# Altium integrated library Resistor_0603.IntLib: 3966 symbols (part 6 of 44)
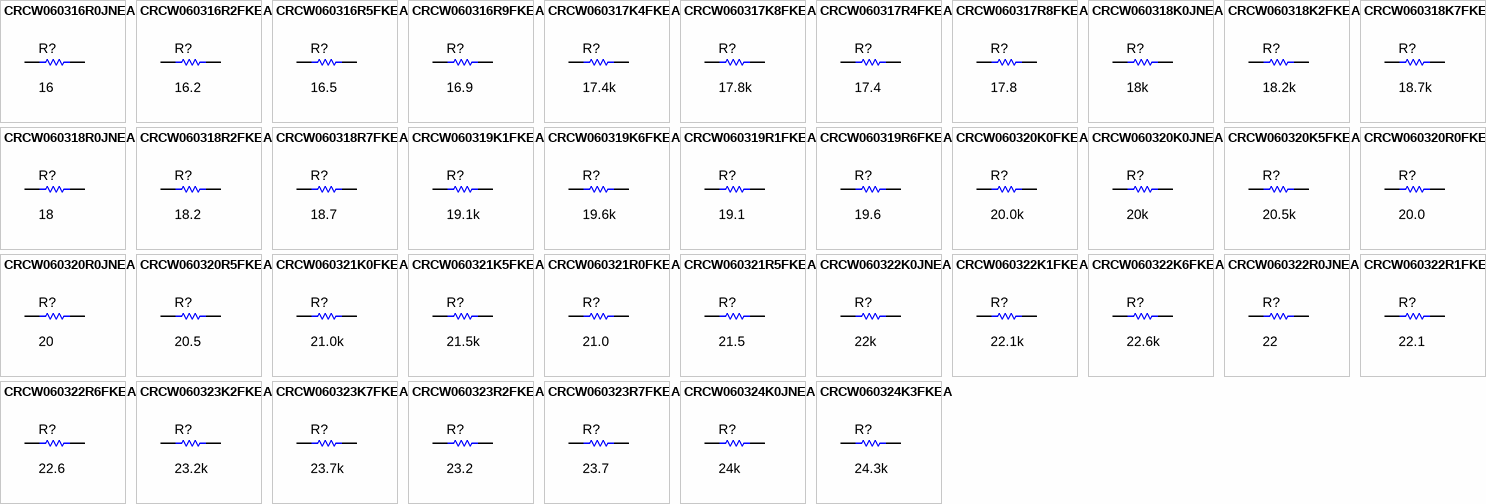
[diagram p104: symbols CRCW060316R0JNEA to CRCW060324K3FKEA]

## CRCW060318K0JNEA
designator R?  ValueDisplayed: 18k  (hidden comment: CRCW060318K0JNEA)
RES, 18 k, 5%, 0.1 W, 0603; Manufacturer: Vishay-Dale; CompType: Resistor; Value: 18k; Res_ohm: 18000; Value_Code: 18k0; Tolerance_%: 5; Power_W: 0.1; Value2: 0.1W; VDC_V: 75; TempCo: 200 ppm/C; SizeArea_mm2: 1.28; SizeX_mm: 1.6; SizeY_mm: 0.8; SizeZ_mm: 1; EIA_Code: E24; U/M: EA; AEC Category: Q200; Green_Lifecycle: Active; Green_REACh: Passed
signal-integrity model Resistor
simulation model Resistor
footprint 0603
footprint 0603M
footprint 0603L
footprint 0603_HV
footprint 0603S
pins: 1, 2

## CRCW060318K2FKEA
designator R?  ValueDisplayed: 18.2k  (hidden comment: CRCW060318K2FKEA)
RES, 18.2 k, 1%, 0.1 W, 0603; Manufacturer: Vishay-Dale; CompType: Resistor; Value: 18.2k; Res_ohm: 18200; Value_Code: 18k2; Tolerance_%: 1; Power_W: 0.1; Value2: 0.1W; VDC_V: 75; TempCo: 100 ppm/C; SizeArea_mm2: 1.28; SizeX_mm: 1.6; SizeY_mm: 0.8; EIA_Code: E96; U/M: EA; AEC Category: Q200; Green_Lifecycle: Active; Green_REACh: Passed
signal-integrity model Resistor
simulation model Resistor
footprint 0603
footprint 0603M
footprint 0603L
footprint 0603_HV
footprint 0603S
pins: 1, 2

## CRCW060318K7FKEA
designator R?  ValueDisplayed: 18.7k  (hidden comment: CRCW060318K7FKEA)
RES, 18.7 k, 1%, 0.1 W, 0603; Manufacturer: Vishay-Dale; CompType: Resistor; Value: 18.7k; Res_ohm: 18700; Value_Code: 18k7; Tolerance_%: 1; Power_W: 0.1; Value2: 0.1W; VDC_V: 75; TempCo: 100 ppm/C; SizeArea_mm2: 1.28; SizeX_mm: 1.6; SizeY_mm: 0.8; EIA_Code: E96; U/M: EA; AEC Category: Q200; Green_Lifecycle: Active; Green_REACh: Passed
signal-integrity model Resistor
simulation model Resistor
footprint 0603
footprint 0603M
footprint 0603L
footprint 0603_HV
footprint 0603S
pins: 1, 2

## CRCW060318R0JNEA
designator R?  ValueDisplayed: 18  (hidden comment: CRCW060318R0JNEA)
RES, 18, 5%, 0.1 W, 0603; Manufacturer: Vishay-Dale; CompType: Resistor; Value: 18; Value_Code: 18R0; Tolerance_%: 5; Power_W: 0.1; Value2: 0.1W; VDC_V: 75; TempCo: 200 ppm/C; SizeArea_mm2: 1.28; SizeX_mm: 1.6; SizeY_mm: 0.8; SizeZ_mm: 1; EIA_Code: E24; U/M: EA; AEC Category: Q200; Green_Lifecycle: Active; Green_REACh: Passed
signal-integrity model Resistor
simulation model Resistor
footprint 0603
footprint 0603M
footprint 0603L
footprint 0603_HV
footprint 0603S
pins: 1, 2

## CRCW060318R2FKEA
designator R?  ValueDisplayed: 18.2  (hidden comment: CRCW060318R2FKEA)
RES, 18.2, 1%, 0.1 W, 0603; Manufacturer: Vishay-Dale; CompType: Resistor; Value: 18.2; Value_Code: 18R2; Tolerance_%: 1; Power_W: 0.1; Value2: 0.1W; VDC_V: 75; TempCo: 100 ppm/C; SizeArea_mm2: 1.28; SizeX_mm: 1.6; SizeY_mm: 0.8; EIA_Code: E96; U/M: EA; AEC Category: Q200
signal-integrity model Resistor
simulation model Resistor
footprint 0603
footprint 0603M
footprint 0603L
footprint 0603_HV
footprint 0603S
pins: 1, 2

## CRCW060318R7FKEA
designator R?  ValueDisplayed: 18.7  (hidden comment: CRCW060318R7FKEA)
RES, 18.7, 1%, 0.1 W, 0603; Manufacturer: Vishay-Dale; CompType: Resistor; Value: 18.7; Value_Code: 18R7; Tolerance_%: 1; Power_W: 0.1; Value2: 0.1W; VDC_V: 75; TempCo: 100 ppm/C; SizeArea_mm2: 1.28; SizeX_mm: 1.6; SizeY_mm: 0.8; EIA_Code: E96; U/M: EA; AEC Category: Q200
signal-integrity model Resistor
simulation model Resistor
footprint 0603
footprint 0603M
footprint 0603L
footprint 0603_HV
footprint 0603S
pins: 1, 2

## CRCW060319K1FKEA
designator R?  ValueDisplayed: 19.1k  (hidden comment: CRCW060319K1FKEA)
RES, 19.1 k, 1%, 0.1 W, 0603; Manufacturer: Vishay-Dale; CompType: Resistor; Value: 19.1k; Res_ohm: 19100; Value_Code: 19k1; Tolerance_%: 1; Power_W: 0.1; Value2: 0.1W; VDC_V: 75; TempCo: 100 ppm/C; SizeArea_mm2: 1.28; SizeX_mm: 1.6; SizeY_mm: 0.8; EIA_Code: E96; U/M: EA; AEC Category: Q200; Green_Lifecycle: Active; Green_REACh: Passed
signal-integrity model Resistor
simulation model Resistor
footprint 0603
footprint 0603M
footprint 0603L
footprint 0603_HV
footprint 0603S
pins: 1, 2

## CRCW060319K6FKEA
designator R?  ValueDisplayed: 19.6k  (hidden comment: CRCW060319K6FKEA)
RES, 19.6 k, 1%, 0.1 W, 0603; Manufacturer: Vishay-Dale; CompType: Resistor; Value: 19.6k; Res_ohm: 19600; Value_Code: 19k6; Tolerance_%: 1; Power_W: 0.1; Value2: 0.1W; VDC_V: 75; TempCo: 100 ppm/C; SizeArea_mm2: 1.28; SizeX_mm: 1.6; SizeY_mm: 0.8; EIA_Code: E96; U/M: EA; AEC Category: Q200; Green_Lifecycle: Active; Green_REACh: Passed
signal-integrity model Resistor
simulation model Resistor
footprint 0603
footprint 0603M
footprint 0603L
footprint 0603_HV
footprint 0603S
pins: 1, 2

## CRCW060319R1FKEA
designator R?  ValueDisplayed: 19.1  (hidden comment: CRCW060319R1FKEA)
RES, 19.1, 1%, 0.1 W, 0603; Manufacturer: Vishay-Dale; CompType: Resistor; Value: 19.1; Value_Code: 19R1; Tolerance_%: 1; Power_W: 0.1; Value2: 0.1W; VDC_V: 75; TempCo: 100 ppm/C; SizeArea_mm2: 1.28; SizeX_mm: 1.6; SizeY_mm: 0.8; EIA_Code: E96; U/M: EA; AEC Category: Q200
signal-integrity model Resistor
simulation model Resistor
footprint 0603
footprint 0603M
footprint 0603L
footprint 0603_HV
footprint 0603S
pins: 1, 2

## CRCW060319R6FKEA
designator R?  ValueDisplayed: 19.6  (hidden comment: CRCW060319R6FKEA)
RES, 19.6, 1%, 0.1 W, 0603; Manufacturer: Vishay-Dale; CompType: Resistor; Value: 19.6; Value_Code: 19R6; Tolerance_%: 1; Power_W: 0.1; Value2: 0.1W; VDC_V: 75; TempCo: 100 ppm/C; SizeArea_mm2: 1.28; SizeX_mm: 1.6; SizeY_mm: 0.8; EIA_Code: E96; U/M: EA; AEC Category: Q200
signal-integrity model Resistor
simulation model Resistor
footprint 0603
footprint 0603M
footprint 0603L
footprint 0603_HV
footprint 0603S
pins: 1, 2

## CRCW060320K0FKEA
designator R?  ValueDisplayed: 20.0k  (hidden comment: CRCW060320K0FKEA)
RES, 20.0 k, 1%, 0.1 W, 0603; Manufacturer: Vishay-Dale; CompType: Resistor; Value: 20.0k; Res_ohm: 20000; Value_Code: 20k0; Tolerance_%: 1; Power_W: 0.1; Value2: 0.1W; VDC_V: 75; TempCo: 100 ppm/C; SizeArea_mm2: 1.28; SizeX_mm: 1.6; SizeY_mm: 0.8; EIA_Code: E96; U/M: EA; AEC Category: Q200; Green_Lifecycle: Active; Green_REACh: Passed
signal-integrity model Resistor
simulation model Resistor
footprint 0603
footprint 0603M
footprint 0603L
footprint 0603_HV
footprint 0603S
pins: 1, 2

## CRCW060320K0JNEA
designator R?  ValueDisplayed: 20k  (hidden comment: CRCW060320K0JNEA)
RES, 20 k, 5%, 0.1 W, 0603; Manufacturer: Vishay-Dale; CompType: Resistor; Value: 20k; Res_ohm: 20000; Value_Code: 20k0; Tolerance_%: 5; Power_W: 0.1; Value2: 0.1W; VDC_V: 75; TempCo: 200 ppm/C; SizeArea_mm2: 1.28; SizeX_mm: 1.6; SizeY_mm: 0.8; SizeZ_mm: 1; EIA_Code: E24; U/M: EA; AEC Category: Q200; Green_Lifecycle: Active; Green_REACh: Passed
signal-integrity model Resistor
simulation model Resistor
footprint 0603
footprint 0603M
footprint 0603L
footprint 0603_HV
footprint 0603S
pins: 1, 2

## CRCW060320K5FKEA
designator R?  ValueDisplayed: 20.5k  (hidden comment: CRCW060320K5FKEA)
RES, 20.5 k, 1%, 0.1 W, 0603; Manufacturer: Vishay-Dale; CompType: Resistor; Value: 20.5k; Res_ohm: 20500; Value_Code: 20k5; Tolerance_%: 1; Power_W: 0.1; Value2: 0.1W; VDC_V: 75; TempCo: 100 ppm/C; SizeArea_mm2: 1.28; SizeX_mm: 1.6; SizeY_mm: 0.8; EIA_Code: E96; U/M: EA; AEC Category: Q200; Green_Lifecycle: Active; Green_REACh: Passed
signal-integrity model Resistor
simulation model Resistor
footprint 0603
footprint 0603M
footprint 0603L
footprint 0603_HV
footprint 0603S
pins: 1, 2

## CRCW060320R0FKEA
designator R?  ValueDisplayed: 20.0  (hidden comment: CRCW060320R0FKEA)
RES, 20.0, 1%, 0.1 W, 0603; Manufacturer: Vishay-Dale; CompType: Resistor; Value: 20.0; Res_ohm: 20; Value_Code: 20R0; Tolerance_%: 1; Power_W: 0.1; Value2: 0.1W; VDC_V: 75; TempCo: 100 ppm/C; SizeArea_mm2: 1.28; SizeX_mm: 1.6; SizeY_mm: 0.8; EIA_Code: E96; U/M: EA; AEC Category: Q200; Green_Lifecycle: Active; Green_REACh: Passed
signal-integrity model Resistor
simulation model Resistor
footprint 0603
footprint 0603M
footprint 0603L
footprint 0603_HV
footprint 0603S
pins: 1, 2

## CRCW060320R0JNEA
designator R?  ValueDisplayed: 20  (hidden comment: CRCW060320R0JNEA)
RES, 20, 5%, 0.1 W, 0603; Manufacturer: Vishay-Dale; CompType: Resistor; Value: 20; Value_Code: 20R0; Tolerance_%: 5; Power_W: 0.1; Value2: 0.1W; VDC_V: 75; TempCo: 200 ppm/C; SizeArea_mm2: 1.28; SizeX_mm: 1.6; SizeY_mm: 0.8; SizeZ_mm: 1; EIA_Code: E24; U/M: EA; AEC Category: Q200
signal-integrity model Resistor
simulation model Resistor
footprint 0603
footprint 0603M
footprint 0603L
footprint 0603_HV
footprint 0603S
pins: 1, 2

## CRCW060320R5FKEA
designator R?  ValueDisplayed: 20.5  (hidden comment: CRCW060320R5FKEA)
RES, 20.5, 1%, 0.1 W, 0603; Manufacturer: Vishay-Dale; CompType: Resistor; Value: 20.5; Value_Code: 20R5; Tolerance_%: 1; Power_W: 0.1; Value2: 0.1W; VDC_V: 75; TempCo: 100 ppm/C; SizeArea_mm2: 1.28; SizeX_mm: 1.6; SizeY_mm: 0.8; EIA_Code: E96; U/M: EA; AEC Category: Q200
signal-integrity model Resistor
simulation model Resistor
footprint 0603
footprint 0603M
footprint 0603L
footprint 0603_HV
footprint 0603S
pins: 1, 2

## CRCW060321K0FKEA
designator R?  ValueDisplayed: 21.0k  (hidden comment: CRCW060321K0FKEA)
RES, 21.0 k, 1%, 0.1 W, 0603; Manufacturer: Vishay-Dale; CompType: Resistor; Value: 21.0k; Res_ohm: 21000; Value_Code: 21k0; Tolerance_%: 1; Power_W: 0.1; Value2: 0.1W; VDC_V: 75; TempCo: 100 ppm/C; SizeArea_mm2: 1.28; SizeX_mm: 1.6; SizeY_mm: 0.8; EIA_Code: E96; U/M: EA; AEC Category: Q200
signal-integrity model Resistor
simulation model Resistor
footprint 0603
footprint 0603M
footprint 0603L
footprint 0603_HV
footprint 0603S
pins: 1, 2

## CRCW060321K5FKEA
designator R?  ValueDisplayed: 21.5k  (hidden comment: CRCW060321K5FKEA)
RES, 21.5 k, 1%, 0.1 W, 0603; Manufacturer: Vishay-Dale; CompType: Resistor; Value: 21.5k; Res_ohm: 21500; Value_Code: 21k5; Tolerance_%: 1; Power_W: 0.1; Value2: 0.1W; VDC_V: 75; TempCo: 100 ppm/C; SizeArea_mm2: 1.28; SizeX_mm: 1.6; SizeY_mm: 0.8; EIA_Code: E96; U/M: EA; AEC Category: Q200; Green_Lifecycle: Active; Green_REACh: Passed
signal-integrity model Resistor
simulation model Resistor
footprint 0603
footprint 0603M
footprint 0603L
footprint 0603_HV
footprint 0603S
pins: 1, 2

## CRCW060321R0FKEA
designator R?  ValueDisplayed: 21.0  (hidden comment: CRCW060321R0FKEA)
RES, 21.0, 1%, 0.1 W, 0603; Manufacturer: Vishay-Dale; CompType: Resistor; Value: 21.0; Res_ohm: 21; Value_Code: 21R0; Tolerance_%: 1; Power_W: 0.1; Value2: 0.1W; VDC_V: 75; TempCo: 100 ppm/C; SizeArea_mm2: 1.28; SizeX_mm: 1.6; SizeY_mm: 0.8; EIA_Code: E96; U/M: EA; AEC Category: Q200
signal-integrity model Resistor
simulation model Resistor
footprint 0603
footprint 0603M
footprint 0603L
footprint 0603_HV
footprint 0603S
pins: 1, 2

## CRCW060321R5FKEA
designator R?  ValueDisplayed: 21.5  (hidden comment: CRCW060321R5FKEA)
RES, 21.5, 1%, 0.1 W, 0603; Manufacturer: Vishay-Dale; CompType: Resistor; Value: 21.5; Value_Code: 21R5; Tolerance_%: 1; Power_W: 0.1; Value2: 0.1W; VDC_V: 75; TempCo: 100 ppm/C; SizeArea_mm2: 1.28; SizeX_mm: 1.6; SizeY_mm: 0.8; EIA_Code: E96; U/M: EA; AEC Category: Q200
signal-integrity model Resistor
simulation model Resistor
footprint 0603
footprint 0603M
footprint 0603L
footprint 0603_HV
footprint 0603S
pins: 1, 2

## CRCW060322K0JNEA
designator R?  ValueDisplayed: 22k  (hidden comment: CRCW060322K0JNEA)
RES, 22 k, 5%, 0.1 W, 0603; Manufacturer: Vishay-Dale; CompType: Resistor; Value: 22k; Res_ohm: 22000; Value_Code: 22k0; Tolerance_%: 5; Power_W: 0.1; Value2: 0.1W; VDC_V: 75; TempCo: 200 ppm/C; SizeArea_mm2: 1.28; SizeX_mm: 1.6; SizeY_mm: 0.8; SizeZ_mm: 1; EIA_Code: E24; U/M: EA; AEC Category: Q200; Green_Lifecycle: Active; Green_REACh: Passed
signal-integrity model Resistor
simulation model Resistor
footprint 0603
footprint 0603M
footprint 0603L
footprint 0603_HV
footprint 0603S
pins: 1, 2

## CRCW060322K1FKEA
designator R?  ValueDisplayed: 22.1k  (hidden comment: CRCW060322K1FKEA)
RES, 22.1 k, 1%, 0.1 W, 0603; Manufacturer: Vishay-Dale; CompType: Resistor; Value: 22.1k; Res_ohm: 22100; Value_Code: 22k1; Tolerance_%: 1; Power_W: 0.1; Value2: 0.1W; VDC_V: 75; TempCo: 100 ppm/C; SizeArea_mm2: 1.28; SizeX_mm: 1.6; SizeY_mm: 0.8; EIA_Code: E96; U/M: EA; AEC Category: Q200; Green_Lifecycle: Active; Green_REACh: Passed
signal-integrity model Resistor
simulation model Resistor
footprint 0603
footprint 0603M
footprint 0603L
footprint 0603_HV
footprint 0603S
pins: 1, 2

## CRCW060322K6FKEA
designator R?  ValueDisplayed: 22.6k  (hidden comment: CRCW060322K6FKEA)
RES, 22.6 k, 1%, 0.1 W, 0603; Manufacturer: Vishay-Dale; CompType: Resistor; Value: 22.6k; Res_ohm: 22600; Value_Code: 22k6; Tolerance_%: 1; Power_W: 0.1; Value2: 0.1W; VDC_V: 75; TempCo: 100 ppm/C; SizeArea_mm2: 1.28; SizeX_mm: 1.6; SizeY_mm: 0.8; EIA_Code: E96; U/M: EA; AEC Category: Q200; Green_Lifecycle: Active; Green_REACh: Passed
signal-integrity model Resistor
simulation model Resistor
footprint 0603
footprint 0603M
footprint 0603L
footprint 0603_HV
footprint 0603S
pins: 1, 2

## CRCW060322R0JNEA
designator R?  ValueDisplayed: 22  (hidden comment: CRCW060322R0JNEA)
RES, 22, 5%, 0.1 W, 0603; Manufacturer: Vishay-Dale; CompType: Resistor; Value: 22; Value_Code: 22R0; Tolerance_%: 5; Power_W: 0.1; Value2: 0.1W; VDC_V: 75; TempCo: 200 ppm/C; SizeArea_mm2: 1.28; SizeX_mm: 1.6; SizeY_mm: 0.8; SizeZ_mm: 1; EIA_Code: E24; U/M: EA; AEC Category: Q200
signal-integrity model Resistor
simulation model Resistor
footprint 0603
footprint 0603M
footprint 0603L
footprint 0603_HV
footprint 0603S
pins: 1, 2

## CRCW060322R1FKEA
designator R?  ValueDisplayed: 22.1  (hidden comment: CRCW060322R1FKEA)
RES, 22.1, 1%, 0.1 W, 0603; Manufacturer: Vishay-Dale; CompType: Resistor; Value: 22.1; Value_Code: 22R1; Tolerance_%: 1; Power_W: 0.1; Value2: 0.1W; VDC_V: 75; TempCo: 100 ppm/C; SizeArea_mm2: 1.28; SizeX_mm: 1.6; SizeY_mm: 0.8; EIA_Code: E96; U/M: EA; AEC Category: Q200; Green_Lifecycle: Active; Green_REACh: Passed
signal-integrity model Resistor
simulation model Resistor
footprint 0603
footprint 0603M
footprint 0603L
footprint 0603_HV
footprint 0603S
pins: 1, 2

## CRCW060322R6FKEA
designator R?  ValueDisplayed: 22.6  (hidden comment: CRCW060322R6FKEA)
RES, 22.6, 1%, 0.1 W, 0603; Manufacturer: Vishay-Dale; CompType: Resistor; Value: 22.6; Value_Code: 22R6; Tolerance_%: 1; Power_W: 0.1; Value2: 0.1W; VDC_V: 75; TempCo: 100 ppm/C; SizeArea_mm2: 1.28; SizeX_mm: 1.6; SizeY_mm: 0.8; EIA_Code: E96; U/M: EA; AEC Category: Q200
signal-integrity model Resistor
simulation model Resistor
footprint 0603
footprint 0603M
footprint 0603L
footprint 0603_HV
footprint 0603S
pins: 1, 2

## CRCW060323K2FKEA
designator R?  ValueDisplayed: 23.2k  (hidden comment: CRCW060323K2FKEA)
RES, 23.2 k, 1%, 0.1 W, 0603; Manufacturer: Vishay-Dale; CompType: Resistor; Value: 23.2k; Res_ohm: 23200; Value_Code: 23k2; Tolerance_%: 1; Power_W: 0.1; Value2: 0.1W; VDC_V: 75; TempCo: 100 ppm/C; SizeArea_mm2: 1.28; SizeX_mm: 1.6; SizeY_mm: 0.8; EIA_Code: E96; U/M: EA; AEC Category: Q200; Green_Lifecycle: Active; Green_REACh: Passed
signal-integrity model Resistor
simulation model Resistor
footprint 0603
footprint 0603M
footprint 0603L
footprint 0603_HV
footprint 0603S
pins: 1, 2

## CRCW060323K7FKEA
designator R?  ValueDisplayed: 23.7k  (hidden comment: CRCW060323K7FKEA)
RES, 23.7 k, 1%, 0.1 W, 0603; Manufacturer: Vishay-Dale; CompType: Resistor; Value: 23.7k; Res_ohm: 23700; Value_Code: 23k7; Tolerance_%: 1; Power_W: 0.1; Value2: 0.1W; VDC_V: 75; TempCo: 100 ppm/C; SizeArea_mm2: 1.28; SizeX_mm: 1.6; SizeY_mm: 0.8; EIA_Code: E96; U/M: EA; AEC Category: Q200
signal-integrity model Resistor
simulation model Resistor
footprint 0603
footprint 0603M
footprint 0603L
footprint 0603_HV
footprint 0603S
pins: 1, 2

## CRCW060323R2FKEA
designator R?  ValueDisplayed: 23.2  (hidden comment: CRCW060323R2FKEA)
RES, 23.2, 1%, 0.1 W, 0603; Manufacturer: Vishay-Dale; CompType: Resistor; Value: 23.2; Value_Code: 23R2; Tolerance_%: 1; Power_W: 0.1; Value2: 0.1W; VDC_V: 75; TempCo: 100 ppm/C; SizeArea_mm2: 1.28; SizeX_mm: 1.6; SizeY_mm: 0.8; EIA_Code: E96; U/M: EA; AEC Category: Q200
signal-integrity model Resistor
simulation model Resistor
footprint 0603
footprint 0603M
footprint 0603L
footprint 0603_HV
footprint 0603S
pins: 1, 2

## CRCW060323R7FKEA
designator R?  ValueDisplayed: 23.7  (hidden comment: CRCW060323R7FKEA)
RES, 23.7, 1%, 0.1 W, 0603; Manufacturer: Vishay-Dale; CompType: Resistor; Value: 23.7; Value_Code: 23R7; Tolerance_%: 1; Power_W: 0.1; Value2: 0.1W; VDC_V: 75; TempCo: 100 ppm/C; SizeArea_mm2: 1.28; SizeX_mm: 1.6; SizeY_mm: 0.8; EIA_Code: E96; U/M: EA; AEC Category: Q200
signal-integrity model Resistor
simulation model Resistor
footprint 0603
footprint 0603M
footprint 0603L
footprint 0603_HV
footprint 0603S
pins: 1, 2

## CRCW060324K0JNEA
designator R?  ValueDisplayed: 24k  (hidden comment: CRCW060324K0JNEA)
RES, 24 k, 5%, 0.1 W, 0603; Manufacturer: Vishay-Dale; CompType: Resistor; Value: 24k; Res_ohm: 24000; Value_Code: 24k0; Tolerance_%: 5; Power_W: 0.1; Value2: 0.1W; VDC_V: 75; TempCo: 200 ppm/C; SizeArea_mm2: 1.28; SizeX_mm: 1.6; SizeY_mm: 0.8; SizeZ_mm: 1; EIA_Code: E24; U/M: EA; AEC Category: Q200
signal-integrity model Resistor
simulation model Resistor
footprint 0603
footprint 0603M
footprint 0603L
footprint 0603_HV
footprint 0603S
pins: 1, 2

## CRCW060324K3FKEA
designator R?  ValueDisplayed: 24.3k  (hidden comment: CRCW060324K3FKEA)
RES, 24.3 k, 1%, 0.1 W, 0603; Manufacturer: Vishay-Dale; CompType: Resistor; Value: 24.3k; Res_ohm: 24300; Value_Code: 24k3; Tolerance_%: 1; Power_W: 0.1; Value2: 0.1W; VDC_V: 75; TempCo: 100 ppm/C; SizeArea_mm2: 1.28; SizeX_mm: 1.6; SizeY_mm: 0.8; EIA_Code: E96; U/M: EA; AEC Category: Q200; Green_Lifecycle: Active; Green_REACh: Passed
signal-integrity model Resistor
simulation model Resistor
footprint 0603
footprint 0603M
footprint 0603L
footprint 0603_HV
footprint 0603S
pins: 1, 2

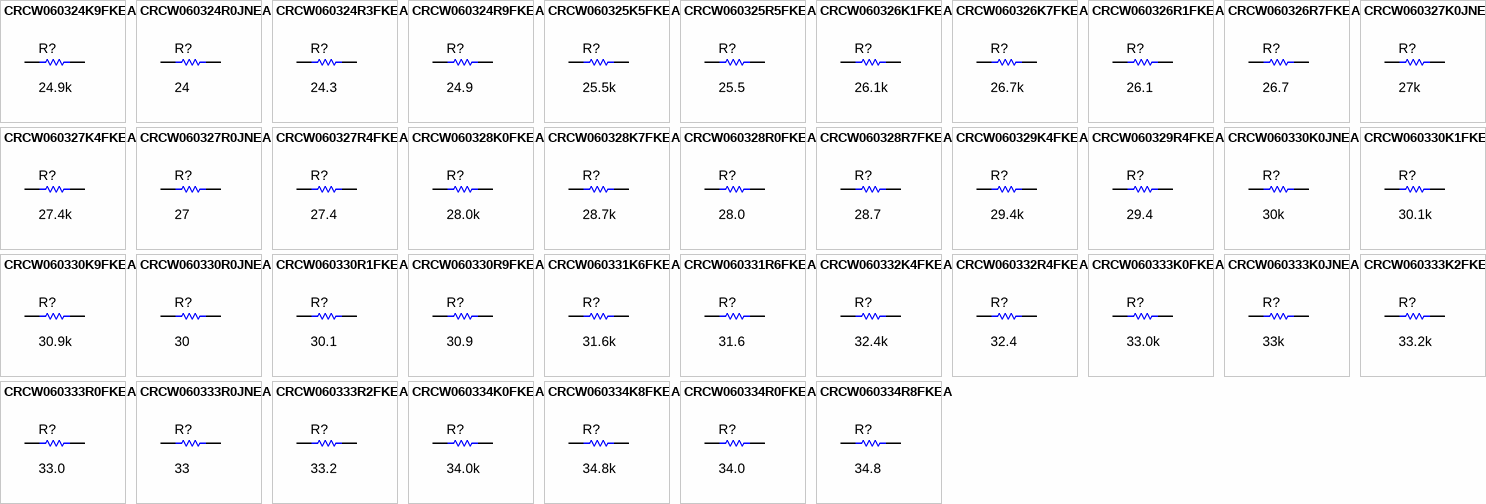
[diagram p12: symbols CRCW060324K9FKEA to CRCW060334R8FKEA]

## CRCW060324K9FKEA
designator R?  ValueDisplayed: 24.9k  (hidden comment: CRCW060324K9FKEA)
RES, 24.9 k, 1%, 0.1 W, 0603; Manufacturer: Vishay-Dale; CompType: Resistor; Value: 24.9k; Res_ohm: 24900; Value_Code: 24k9; Tolerance_%: 1; Power_W: 0.1; Value2: 0.1W; VDC_V: 75; TempCo: 100 ppm/C; SizeArea_mm2: 1.28; SizeX_mm: 1.6; SizeY_mm: 0.8; EIA_Code: E96; U/M: EA; AEC Category: Q200; Green_Lifecycle: Active; Green_REACh: Passed
signal-integrity model Resistor
simulation model Resistor
footprint 0603
footprint 0603M
footprint 0603L
footprint 0603_HV
footprint 0603S
pins: 1, 2

## CRCW060324R0JNEA
designator R?  ValueDisplayed: 24  (hidden comment: CRCW060324R0JNEA)
RES, 24, 5%, 0.1 W, 0603; Manufacturer: Vishay-Dale; CompType: Resistor; Value: 24; Value_Code: 24R0; Tolerance_%: 5; Power_W: 0.1; Value2: 0.1W; VDC_V: 75; TempCo: 200 ppm/C; SizeArea_mm2: 1.28; SizeX_mm: 1.6; SizeY_mm: 0.8; SizeZ_mm: 1; EIA_Code: E24; U/M: EA; AEC Category: Q200
signal-integrity model Resistor
simulation model Resistor
footprint 0603
footprint 0603M
footprint 0603L
footprint 0603_HV
footprint 0603S
pins: 1, 2

## CRCW060324R3FKEA
designator R?  ValueDisplayed: 24.3  (hidden comment: CRCW060324R3FKEA)
RES, 24.3, 1%, 0.1 W, 0603; Manufacturer: Vishay-Dale; CompType: Resistor; Value: 24.3; Value_Code: 24R3; Tolerance_%: 1; Power_W: 0.1; Value2: 0.1W; VDC_V: 75; TempCo: 100 ppm/C; SizeArea_mm2: 1.28; SizeX_mm: 1.6; SizeY_mm: 0.8; EIA_Code: E96; U/M: EA; AEC Category: Q200
signal-integrity model Resistor
simulation model Resistor
footprint 0603
footprint 0603M
footprint 0603L
footprint 0603_HV
footprint 0603S
pins: 1, 2

## CRCW060324R9FKEA
designator R?  ValueDisplayed: 24.9  (hidden comment: CRCW060324R9FKEA)
RES, 24.9, 1%, 0.1 W, 0603; Manufacturer: Vishay-Dale; CompType: Resistor; Value: 24.9; Value_Code: 24R9; Tolerance_%: 1; Power_W: 0.1; Value2: 0.1W; VDC_V: 75; TempCo: 100 ppm/C; SizeArea_mm2: 1.28; SizeX_mm: 1.6; SizeY_mm: 0.8; EIA_Code: E96; U/M: EA; AEC Category: Q200
signal-integrity model Resistor
simulation model Resistor
footprint 0603
footprint 0603M
footprint 0603L
footprint 0603_HV
footprint 0603S
pins: 1, 2

## CRCW060325K5FKEA
designator R?  ValueDisplayed: 25.5k  (hidden comment: CRCW060325K5FKEA)
RES, 25.5 k, 1%, 0.1 W, 0603; Manufacturer: Vishay-Dale; CompType: Resistor; Value: 25.5k; Res_ohm: 25500; Value_Code: 25k5; Tolerance_%: 1; Power_W: 0.1; Value2: 0.1W; VDC_V: 75; TempCo: 100 ppm/C; SizeArea_mm2: 1.28; SizeX_mm: 1.6; SizeY_mm: 0.8; EIA_Code: E96; U/M: EA; AEC Category: Q200; Green_Lifecycle: Active; Green_REACh: Passed
signal-integrity model Resistor
simulation model Resistor
footprint 0603
footprint 0603M
footprint 0603L
footprint 0603_HV
footprint 0603S
pins: 1, 2

## CRCW060325R5FKEA
designator R?  ValueDisplayed: 25.5  (hidden comment: CRCW060325R5FKEA)
RES, 25.5, 1%, 0.1 W, 0603; Manufacturer: Vishay-Dale; CompType: Resistor; Value: 25.5; Value_Code: 25R5; Tolerance_%: 1; Power_W: 0.1; Value2: 0.1W; VDC_V: 75; TempCo: 100 ppm/C; SizeArea_mm2: 1.28; SizeX_mm: 1.6; SizeY_mm: 0.8; EIA_Code: E96; U/M: EA; AEC Category: Q200
signal-integrity model Resistor
simulation model Resistor
footprint 0603
footprint 0603M
footprint 0603L
footprint 0603_HV
footprint 0603S
pins: 1, 2

## CRCW060326K1FKEA
designator R?  ValueDisplayed: 26.1k  (hidden comment: CRCW060326K1FKEA)
RES, 26.1 k, 1%, 0.1 W, 0603; Manufacturer: Vishay-Dale; CompType: Resistor; Value: 26.1k; Res_ohm: 26100; Value_Code: 26k1; Tolerance_%: 1; Power_W: 0.1; Value2: 0.1W; VDC_V: 75; TempCo: 100 ppm/C; SizeArea_mm2: 1.28; SizeX_mm: 1.6; SizeY_mm: 0.8; EIA_Code: E96; U/M: EA; AEC Category: Q200; Green_Lifecycle: Active; Green_REACh: Passed
signal-integrity model Resistor
simulation model Resistor
footprint 0603
footprint 0603M
footprint 0603L
footprint 0603_HV
footprint 0603S
pins: 1, 2

## CRCW060326K7FKEA
designator R?  ValueDisplayed: 26.7k  (hidden comment: CRCW060326K7FKEA)
RES, 26.7 k, 1%, 0.1 W, 0603; Manufacturer: Vishay-Dale; CompType: Resistor; Value: 26.7k; Res_ohm: 26700; Value_Code: 26k7; Tolerance_%: 1; Power_W: 0.1; Value2: 0.1W; VDC_V: 75; TempCo: 100 ppm/C; SizeArea_mm2: 1.28; SizeX_mm: 1.6; SizeY_mm: 0.8; EIA_Code: E96; U/M: EA; AEC Category: Q200; Green_Lifecycle: Active; Green_REACh: Passed
signal-integrity model Resistor
simulation model Resistor
footprint 0603
footprint 0603M
footprint 0603L
footprint 0603_HV
footprint 0603S
pins: 1, 2

## CRCW060326R1FKEA
designator R?  ValueDisplayed: 26.1  (hidden comment: CRCW060326R1FKEA)
RES, 26.1, 1%, 0.1 W, 0603; Manufacturer: Vishay-Dale; CompType: Resistor; Value: 26.1; Value_Code: 26R1; Tolerance_%: 1; Power_W: 0.1; Value2: 0.1W; VDC_V: 75; TempCo: 100 ppm/C; SizeArea_mm2: 1.28; SizeX_mm: 1.6; SizeY_mm: 0.8; EIA_Code: E96; U/M: EA; AEC Category: Q200
signal-integrity model Resistor
simulation model Resistor
footprint 0603
footprint 0603M
footprint 0603L
footprint 0603_HV
footprint 0603S
pins: 1, 2

## CRCW060326R7FKEA
designator R?  ValueDisplayed: 26.7  (hidden comment: CRCW060326R7FKEA)
RES, 26.7, 1%, 0.1 W, 0603; Manufacturer: Vishay-Dale; CompType: Resistor; Value: 26.7; Value_Code: 26R7; Tolerance_%: 1; Power_W: 0.1; Value2: 0.1W; VDC_V: 75; TempCo: 100 ppm/C; SizeArea_mm2: 1.28; SizeX_mm: 1.6; SizeY_mm: 0.8; EIA_Code: E96; U/M: EA; AEC Category: Q200
signal-integrity model Resistor
simulation model Resistor
footprint 0603
footprint 0603M
footprint 0603L
footprint 0603_HV
footprint 0603S
pins: 1, 2

## CRCW060327K0JNEA
designator R?  ValueDisplayed: 27k  (hidden comment: CRCW060327K0JNEA)
RES, 27 k, 5%, 0.1 W, 0603; Manufacturer: Vishay-Dale; CompType: Resistor; Value: 27k; Res_ohm: 27000; Value_Code: 27k0; Tolerance_%: 5; Power_W: 0.1; Value2: 0.1W; VDC_V: 75; TempCo: 200 ppm/C; SizeArea_mm2: 1.28; SizeX_mm: 1.6; SizeY_mm: 0.8; SizeZ_mm: 1; EIA_Code: E24; U/M: EA; AEC Category: Q200; Green_Lifecycle: Active; Green_REACh: Passed
signal-integrity model Resistor
simulation model Resistor
footprint 0603
footprint 0603M
footprint 0603L
footprint 0603_HV
footprint 0603S
pins: 1, 2

## CRCW060327K4FKEA
designator R?  ValueDisplayed: 27.4k  (hidden comment: CRCW060327K4FKEA)
RES, 27.4 k, 1%, 0.1 W, 0603; Manufacturer: Vishay-Dale; CompType: Resistor; Value: 27.4k; Res_ohm: 27400; Value_Code: 27k4; Tolerance_%: 1; Power_W: 0.1; Value2: 0.1W; VDC_V: 75; TempCo: 100 ppm/C; SizeArea_mm2: 1.28; SizeX_mm: 1.6; SizeY_mm: 0.8; EIA_Code: E96; U/M: EA; AEC Category: Q200; Green_Lifecycle: Active; Green_REACh: Passed
signal-integrity model Resistor
simulation model Resistor
footprint 0603
footprint 0603M
footprint 0603L
footprint 0603_HV
footprint 0603S
pins: 1, 2

## CRCW060327R0JNEA
designator R?  ValueDisplayed: 27  (hidden comment: CRCW060327R0JNEA)
RES, 27, 5%, 0.1 W, 0603; Manufacturer: Vishay-Dale; CompType: Resistor; Value: 27; Value_Code: 27R0; Tolerance_%: 5; Power_W: 0.1; Value2: 0.1W; VDC_V: 75; TempCo: 200 ppm/C; SizeArea_mm2: 1.28; SizeX_mm: 1.6; SizeY_mm: 0.8; SizeZ_mm: 1; EIA_Code: E24; U/M: EA; AEC Category: Q200; Green_Lifecycle: Active; Green_REACh: Passed
signal-integrity model Resistor
simulation model Resistor
footprint 0603
footprint 0603M
footprint 0603L
footprint 0603_HV
footprint 0603S
pins: 1, 2

## CRCW060327R4FKEA
designator R?  ValueDisplayed: 27.4  (hidden comment: CRCW060327R4FKEA)
RES, 27.4, 1%, 0.1 W, 0603; Manufacturer: Vishay-Dale; CompType: Resistor; Value: 27.4; Value_Code: 27R4; Tolerance_%: 1; Power_W: 0.1; Value2: 0.1W; VDC_V: 75; TempCo: 100 ppm/C; SizeArea_mm2: 1.28; SizeX_mm: 1.6; SizeY_mm: 0.8; EIA_Code: E96; U/M: EA; AEC Category: Q200; Green_Lifecycle: Active; Green_REACh: Passed
signal-integrity model Resistor
simulation model Resistor
footprint 0603
footprint 0603M
footprint 0603L
footprint 0603_HV
footprint 0603S
pins: 1, 2

## CRCW060328K0FKEA
designator R?  ValueDisplayed: 28.0k  (hidden comment: CRCW060328K0FKEA)
RES, 28.0 k, 1%, 0.1 W, 0603; Manufacturer: Vishay-Dale; CompType: Resistor; Value: 28.0k; Res_ohm: 28000; Value_Code: 28k0; Tolerance_%: 1; Power_W: 0.1; Value2: 0.1W; VDC_V: 75; TempCo: 100 ppm/C; SizeArea_mm2: 1.28; SizeX_mm: 1.6; SizeY_mm: 0.8; EIA_Code: E96; U/M: EA; AEC Category: Q200; Green_Lifecycle: Active; Green_REACh: Passed
signal-integrity model Resistor
simulation model Resistor
footprint 0603
footprint 0603M
footprint 0603L
footprint 0603_HV
footprint 0603S
pins: 1, 2

## CRCW060328K7FKEA
designator R?  ValueDisplayed: 28.7k  (hidden comment: CRCW060328K7FKEA)
RES, 28.7 k, 1%, 0.1 W, 0603; Manufacturer: Vishay-Dale; CompType: Resistor; Value: 28.7k; Res_ohm: 28700; Value_Code: 28k7; Tolerance_%: 1; Power_W: 0.1; Value2: 0.1W; VDC_V: 75; TempCo: 100 ppm/C; SizeArea_mm2: 1.28; SizeX_mm: 1.6; SizeY_mm: 0.8; EIA_Code: E96; U/M: EA; AEC Category: Q200
signal-integrity model Resistor
simulation model Resistor
footprint 0603
footprint 0603M
footprint 0603L
footprint 0603_HV
footprint 0603S
pins: 1, 2

## CRCW060328R0FKEA
designator R?  ValueDisplayed: 28.0  (hidden comment: CRCW060328R0FKEA)
RES, 28.0, 1%, 0.1 W, 0603; Manufacturer: Vishay-Dale; CompType: Resistor; Value: 28.0; Res_ohm: 28; Value_Code: 28R0; Tolerance_%: 1; Power_W: 0.1; Value2: 0.1W; VDC_V: 75; TempCo: 100 ppm/C; SizeArea_mm2: 1.28; SizeX_mm: 1.6; SizeY_mm: 0.8; EIA_Code: E96; U/M: EA; AEC Category: Q200
signal-integrity model Resistor
simulation model Resistor
footprint 0603
footprint 0603M
footprint 0603L
footprint 0603_HV
footprint 0603S
pins: 1, 2

## CRCW060328R7FKEA
designator R?  ValueDisplayed: 28.7  (hidden comment: CRCW060328R7FKEA)
RES, 28.7, 1%, 0.1 W, 0603; Manufacturer: Vishay-Dale; CompType: Resistor; Value: 28.7; Value_Code: 28R7; Tolerance_%: 1; Power_W: 0.1; Value2: 0.1W; VDC_V: 75; TempCo: 100 ppm/C; SizeArea_mm2: 1.28; SizeX_mm: 1.6; SizeY_mm: 0.8; EIA_Code: E96; U/M: EA; AEC Category: Q200
signal-integrity model Resistor
simulation model Resistor
footprint 0603
footprint 0603M
footprint 0603L
footprint 0603_HV
footprint 0603S
pins: 1, 2

## CRCW060329K4FKEA
designator R?  ValueDisplayed: 29.4k  (hidden comment: CRCW060329K4FKEA)
RES, 29.4 k, 1%, 0.1 W, 0603; Manufacturer: Vishay-Dale; CompType: Resistor; Value: 29.4k; Res_ohm: 29400; Value_Code: 29k4; Tolerance_%: 1; Power_W: 0.1; Value2: 0.1W; VDC_V: 75; TempCo: 100 ppm/C; SizeArea_mm2: 1.28; SizeX_mm: 1.6; SizeY_mm: 0.8; EIA_Code: E96; U/M: EA; AEC Category: Q200; Green_Lifecycle: Active; Green_REACh: Passed
signal-integrity model Resistor
simulation model Resistor
footprint 0603
footprint 0603M
footprint 0603L
footprint 0603_HV
footprint 0603S
pins: 1, 2

## CRCW060329R4FKEA
designator R?  ValueDisplayed: 29.4  (hidden comment: CRCW060329R4FKEA)
RES, 29.4, 1%, 0.1 W, 0603; Manufacturer: Vishay-Dale; CompType: Resistor; Value: 29.4; Value_Code: 29R4; Tolerance_%: 1; Power_W: 0.1; Value2: 0.1W; VDC_V: 75; TempCo: 100 ppm/C; SizeArea_mm2: 1.28; SizeX_mm: 1.6; SizeY_mm: 0.8; EIA_Code: E96; U/M: EA; AEC Category: Q200
signal-integrity model Resistor
simulation model Resistor
footprint 0603
footprint 0603M
footprint 0603L
footprint 0603_HV
footprint 0603S
pins: 1, 2

## CRCW060330K0JNEA
designator R?  ValueDisplayed: 30k  (hidden comment: CRCW060330K0JNEA)
RES, 30 k, 5%, 0.1 W, 0603; Manufacturer: Vishay-Dale; CompType: Resistor; Value: 30k; Res_ohm: 30000; Value_Code: 30k0; Tolerance_%: 5; Power_W: 0.1; Value2: 0.1W; VDC_V: 75; TempCo: 200 ppm/C; SizeArea_mm2: 1.28; SizeX_mm: 1.6; SizeY_mm: 0.8; SizeZ_mm: 1; EIA_Code: E24; U/M: EA; AEC Category: Q200; Green_Lifecycle: Active; Green_REACh: Passed
signal-integrity model Resistor
simulation model Resistor
footprint 0603
footprint 0603M
footprint 0603L
footprint 0603_HV
footprint 0603S
pins: 1, 2

## CRCW060330K1FKEA
designator R?  ValueDisplayed: 30.1k  (hidden comment: CRCW060330K1FKEA)
RES, 30.1 k, 1%, 0.1 W, 0603; Manufacturer: Vishay-Dale; CompType: Resistor; Value: 30.1k; Res_ohm: 30100; Value_Code: 30k1; Tolerance_%: 1; Power_W: 0.1; Value2: 0.1W; VDC_V: 75; TempCo: 100 ppm/C; SizeArea_mm2: 1.28; SizeX_mm: 1.6; SizeY_mm: 0.8; EIA_Code: E96; U/M: EA; AEC Category: Q200; Green_Lifecycle: Active; Green_REACh: Passed
signal-integrity model Resistor
simulation model Resistor
footprint 0603
footprint 0603M
footprint 0603L
footprint 0603_HV
footprint 0603S
pins: 1, 2

## CRCW060330K9FKEA
designator R?  ValueDisplayed: 30.9k  (hidden comment: CRCW060330K9FKEA)
RES, 30.9 k, 1%, 0.1 W, 0603; Manufacturer: Vishay-Dale; CompType: Resistor; Value: 30.9k; Res_ohm: 30900; Value_Code: 30k9; Tolerance_%: 1; Power_W: 0.1; Value2: 0.1W; VDC_V: 75; TempCo: 100 ppm/C; SizeArea_mm2: 1.28; SizeX_mm: 1.6; SizeY_mm: 0.8; EIA_Code: E96; U/M: EA; AEC Category: Q200; Green_Lifecycle: Active; Green_REACh: Passed
signal-integrity model Resistor
simulation model Resistor
footprint 0603
footprint 0603M
footprint 0603L
footprint 0603_HV
footprint 0603S
pins: 1, 2

## CRCW060330R0JNEA
designator R?  ValueDisplayed: 30  (hidden comment: CRCW060330R0JNEA)
RES, 30, 5%, 0.1 W, 0603; Manufacturer: Vishay-Dale; CompType: Resistor; Value: 30; Value_Code: 30R0; Tolerance_%: 5; Power_W: 0.1; Value2: 0.1W; VDC_V: 75; TempCo: 200 ppm/C; SizeArea_mm2: 1.28; SizeX_mm: 1.6; SizeY_mm: 0.8; SizeZ_mm: 1; EIA_Code: E24; U/M: EA; AEC Category: Q200
signal-integrity model Resistor
simulation model Resistor
footprint 0603
footprint 0603M
footprint 0603L
footprint 0603_HV
footprint 0603S
pins: 1, 2

## CRCW060330R1FKEA
designator R?  ValueDisplayed: 30.1  (hidden comment: CRCW060330R1FKEA)
RES, 30.1, 1%, 0.1 W, 0603; Manufacturer: Vishay-Dale; CompType: Resistor; Value: 30.1; Value_Code: 30R1; Tolerance_%: 1; Power_W: 0.1; Value2: 0.1W; VDC_V: 75; TempCo: 100 ppm/C; SizeArea_mm2: 1.28; SizeX_mm: 1.6; SizeY_mm: 0.8; EIA_Code: E96; U/M: EA; AEC Category: Q200; Green_Lifecycle: Active; Green_REACh: Passed
signal-integrity model Resistor
simulation model Resistor
footprint 0603
footprint 0603M
footprint 0603L
footprint 0603_HV
footprint 0603S
pins: 1, 2

## CRCW060330R9FKEA
designator R?  ValueDisplayed: 30.9  (hidden comment: CRCW060330R9FKEA)
RES, 30.9, 1%, 0.1 W, 0603; Manufacturer: Vishay-Dale; CompType: Resistor; Value: 30.9; Value_Code: 30R9; Tolerance_%: 1; Power_W: 0.1; Value2: 0.1W; VDC_V: 75; TempCo: 100 ppm/C; SizeArea_mm2: 1.28; SizeX_mm: 1.6; SizeY_mm: 0.8; EIA_Code: E96; U/M: EA; AEC Category: Q200
signal-integrity model Resistor
simulation model Resistor
footprint 0603
footprint 0603M
footprint 0603L
footprint 0603_HV
footprint 0603S
pins: 1, 2

## CRCW060331K6FKEA
designator R?  ValueDisplayed: 31.6k  (hidden comment: CRCW060331K6FKEA)
RES, 31.6 k, 1%, 0.1 W, 0603; Manufacturer: Vishay-Dale; CompType: Resistor; Value: 31.6k; Res_ohm: 31600; Value_Code: 31k6; Tolerance_%: 1; Power_W: 0.1; Value2: 0.1W; VDC_V: 75; TempCo: 100 ppm/C; SizeArea_mm2: 1.28; SizeX_mm: 1.6; SizeY_mm: 0.8; EIA_Code: E96; U/M: EA; AEC Category: Q200; Green_Lifecycle: Active; Green_REACh: Passed
signal-integrity model Resistor
simulation model Resistor
footprint 0603
footprint 0603M
footprint 0603L
footprint 0603_HV
footprint 0603S
pins: 1, 2

## CRCW060331R6FKEA
designator R?  ValueDisplayed: 31.6  (hidden comment: CRCW060331R6FKEA)
RES, 31.6, 1%, 0.1 W, 0603; Manufacturer: Vishay-Dale; CompType: Resistor; Value: 31.6; Value_Code: 31R6; Tolerance_%: 1; Power_W: 0.1; Value2: 0.1W; VDC_V: 75; TempCo: 100 ppm/C; SizeArea_mm2: 1.28; SizeX_mm: 1.6; SizeY_mm: 0.8; EIA_Code: E96; U/M: EA; AEC Category: Q200
signal-integrity model Resistor
simulation model Resistor
footprint 0603
footprint 0603M
footprint 0603L
footprint 0603_HV
footprint 0603S
pins: 1, 2

## CRCW060332K4FKEA
designator R?  ValueDisplayed: 32.4k  (hidden comment: CRCW060332K4FKEA)
RES, 32.4 k, 1%, 0.1 W, 0603; Manufacturer: Vishay-Dale; CompType: Resistor; Value: 32.4k; Res_ohm: 32400; Value_Code: 32k4; Tolerance_%: 1; Power_W: 0.1; Value2: 0.1W; VDC_V: 75; TempCo: 100 ppm/C; SizeArea_mm2: 1.28; SizeX_mm: 1.6; SizeY_mm: 0.8; EIA_Code: E96; U/M: EA; AEC Category: Q200; Green_Lifecycle: Active; Green_REACh: Passed
signal-integrity model Resistor
simulation model Resistor
footprint 0603
footprint 0603M
footprint 0603L
footprint 0603_HV
footprint 0603S
pins: 1, 2

## CRCW060332R4FKEA
designator R?  ValueDisplayed: 32.4  (hidden comment: CRCW060332R4FKEA)
RES, 32.4, 1%, 0.1 W, 0603; Manufacturer: Vishay-Dale; CompType: Resistor; Value: 32.4; Value_Code: 32R4; Tolerance_%: 1; Power_W: 0.1; Value2: 0.1W; VDC_V: 75; TempCo: 100 ppm/C; SizeArea_mm2: 1.28; SizeX_mm: 1.6; SizeY_mm: 0.8; EIA_Code: E96; U/M: EA; AEC Category: Q200
signal-integrity model Resistor
simulation model Resistor
footprint 0603
footprint 0603M
footprint 0603L
footprint 0603_HV
footprint 0603S
pins: 1, 2

## CRCW060333K0FKEA
designator R?  ValueDisplayed: 33.0k  (hidden comment: CRCW060333K0FKEA)
RES, 33.0 k, 1%, 0.1 W, 0603; Manufacturer: Vishay-Dale; CompType: Resistor; Value: 33.0k; Res_ohm: 33000; Value_Code: 33k0; Tolerance_%: 1; Power_W: 0.1; Value2: 0.1W; VDC_V: 75; TempCo: 100 ppm/C; SizeArea_mm2: 1.28; SizeX_mm: 1.6; SizeY_mm: 0.8; U/M: EA; AEC Category: Q200; Green_Lifecycle: Active; Green_REACh: Passed
signal-integrity model Resistor
simulation model Resistor
footprint 0603
footprint 0603M
footprint 0603L
footprint 0603_HV
footprint 0603S
pins: 1, 2

## CRCW060333K0JNEA
designator R?  ValueDisplayed: 33k  (hidden comment: CRCW060333K0JNEA)
RES, 33 k, 5%, 0.1 W, 0603; Manufacturer: Vishay-Dale; CompType: Resistor; Value: 33k; Res_ohm: 33000; Value_Code: 33k0; Tolerance_%: 5; Power_W: 0.1; Value2: 0.1W; VDC_V: 75; TempCo: 200 ppm/C; SizeArea_mm2: 1.28; SizeX_mm: 1.6; SizeY_mm: 0.8; SizeZ_mm: 1; EIA_Code: E24; U/M: EA; AEC Category: Q200; Green_Lifecycle: Active; Green_REACh: Passed
signal-integrity model Resistor
simulation model Resistor
footprint 0603
footprint 0603M
footprint 0603L
footprint 0603_HV
footprint 0603S
pins: 1, 2

## CRCW060333K2FKEA
designator R?  ValueDisplayed: 33.2k  (hidden comment: CRCW060333K2FKEA)
RES, 33.2 k, 1%, 0.1 W, 0603; Manufacturer: Vishay-Dale; CompType: Resistor; Value: 33.2k; Res_ohm: 33200; Value_Code: 33k2; Tolerance_%: 1; Power_W: 0.1; Value2: 0.1W; VDC_V: 75; TempCo: 100 ppm/C; SizeArea_mm2: 1.28; SizeX_mm: 1.6; SizeY_mm: 0.8; EIA_Code: E96; U/M: EA; AEC Category: Q200; Green_Lifecycle: Active; Green_REACh: Passed
signal-integrity model Resistor
simulation model Resistor
footprint 0603
footprint 0603M
footprint 0603L
footprint 0603_HV
footprint 0603S
pins: 1, 2

## CRCW060333R0FKEA
designator R?  ValueDisplayed: 33.0  (hidden comment: CRCW060333R0FKEA)
RES, 33.0, 1%, 0.1 W, 0603; Manufacturer: Vishay-Dale; CompType: Resistor; Value: 33.0; Res_ohm: 33; Value_Code: 33R0; Tolerance_%: 1; Power_W: 0.1; Value2: 0.1W; VDC_V: 75; TempCo: 100 ppm/C; SizeArea_mm2: 1.28; SizeX_mm: 1.6; SizeY_mm: 0.8; U/M: EA; AEC Category: Q200; Green_Lifecycle: Active; Green_REACh: Passed
signal-integrity model Resistor
simulation model Resistor
footprint 0603
footprint 0603M
footprint 0603L
footprint 0603_HV
footprint 0603S
pins: 1, 2

## CRCW060333R0JNEA
designator R?  ValueDisplayed: 33  (hidden comment: CRCW060333R0JNEA)
RES, 33, 5%, 0.1 W, 0603; Manufacturer: Vishay-Dale; CompType: Resistor; Value: 33; Value_Code: 33R0; Tolerance_%: 5; Power_W: 0.1; Value2: 0.1W; VDC_V: 75; TempCo: 200 ppm/C; SizeArea_mm2: 1.28; SizeX_mm: 1.6; SizeY_mm: 0.8; SizeZ_mm: 1; EIA_Code: E24; U/M: EA; AEC Category: Q200; Green_Lifecycle: Active; Green_REACh: Passed
signal-integrity model Resistor
simulation model Resistor
footprint 0603
footprint 0603M
footprint 0603L
footprint 0603_HV
footprint 0603S
pins: 1, 2

## CRCW060333R2FKEA
designator R?  ValueDisplayed: 33.2  (hidden comment: CRCW060333R2FKEA)
RES, 33.2, 1%, 0.1 W, 0603; Manufacturer: Vishay-Dale; CompType: Resistor; Value: 33.2; Value_Code: 33R2; Tolerance_%: 1; Power_W: 0.1; Value2: 0.1W; VDC_V: 75; TempCo: 100 ppm/C; SizeArea_mm2: 1.28; SizeX_mm: 1.6; SizeY_mm: 0.8; EIA_Code: E96; U/M: EA; AEC Category: Q200
signal-integrity model Resistor
simulation model Resistor
footprint 0603
footprint 0603M
footprint 0603L
footprint 0603_HV
footprint 0603S
pins: 1, 2

## CRCW060334K0FKEA
designator R?  ValueDisplayed: 34.0k  (hidden comment: CRCW060334K0FKEA)
RES, 34.0 k, 1%, 0.1 W, 0603; Manufacturer: Vishay-Dale; CompType: Resistor; Value: 34.0k; Res_ohm: 34000; Value_Code: 34k0; Tolerance_%: 1; Power_W: 0.1; Value2: 0.1W; VDC_V: 75; TempCo: 100 ppm/C; SizeArea_mm2: 1.28; SizeX_mm: 1.6; SizeY_mm: 0.8; EIA_Code: E96; U/M: EA; AEC Category: Q200
signal-integrity model Resistor
simulation model Resistor
footprint 0603
footprint 0603M
footprint 0603L
footprint 0603_HV
footprint 0603S
pins: 1, 2

## CRCW060334K8FKEA
designator R?  ValueDisplayed: 34.8k  (hidden comment: CRCW060334K8FKEA)
RES, 34.8 k, 1%, 0.1 W, 0603; Manufacturer: Vishay-Dale; CompType: Resistor; Value: 34.8k; Res_ohm: 34800; Value_Code: 34k8; Tolerance_%: 1; Power_W: 0.1; Value2: 0.1W; VDC_V: 75; TempCo: 100 ppm/C; SizeArea_mm2: 1.28; SizeX_mm: 1.6; SizeY_mm: 0.8; EIA_Code: E96; U/M: EA; AEC Category: Q200; Green_Lifecycle: Active; Green_REACh: Passed
signal-integrity model Resistor
simulation model Resistor
footprint 0603
footprint 0603M
footprint 0603L
footprint 0603_HV
footprint 0603S
pins: 1, 2

## CRCW060334R0FKEA
designator R?  ValueDisplayed: 34.0  (hidden comment: CRCW060334R0FKEA)
RES, 34.0, 1%, 0.1 W, 0603; Manufacturer: Vishay-Dale; CompType: Resistor; Value: 34.0; Res_ohm: 34; Value_Code: 34R0; Tolerance_%: 1; Power_W: 0.1; Value2: 0.1W; VDC_V: 75; TempCo: 100 ppm/C; SizeArea_mm2: 1.28; SizeX_mm: 1.6; SizeY_mm: 0.8; EIA_Code: E96; U/M: EA; AEC Category: Q200
signal-integrity model Resistor
simulation model Resistor
footprint 0603
footprint 0603M
footprint 0603L
footprint 0603_HV
footprint 0603S
pins: 1, 2

## CRCW060334R8FKEA
designator R?  ValueDisplayed: 34.8  (hidden comment: CRCW060334R8FKEA)
RES, 34.8, 1%, 0.1 W, 0603; Manufacturer: Vishay-Dale; CompType: Resistor; Value: 34.8; Value_Code: 34R8; Tolerance_%: 1; Power_W: 0.1; Value2: 0.1W; VDC_V: 75; TempCo: 100 ppm/C; SizeArea_mm2: 1.28; SizeX_mm: 1.6; SizeY_mm: 0.8; EIA_Code: E96; U/M: EA; AEC Category: Q200
signal-integrity model Resistor
simulation model Resistor
footprint 0603
footprint 0603M
footprint 0603L
footprint 0603_HV
footprint 0603S
pins: 1, 2

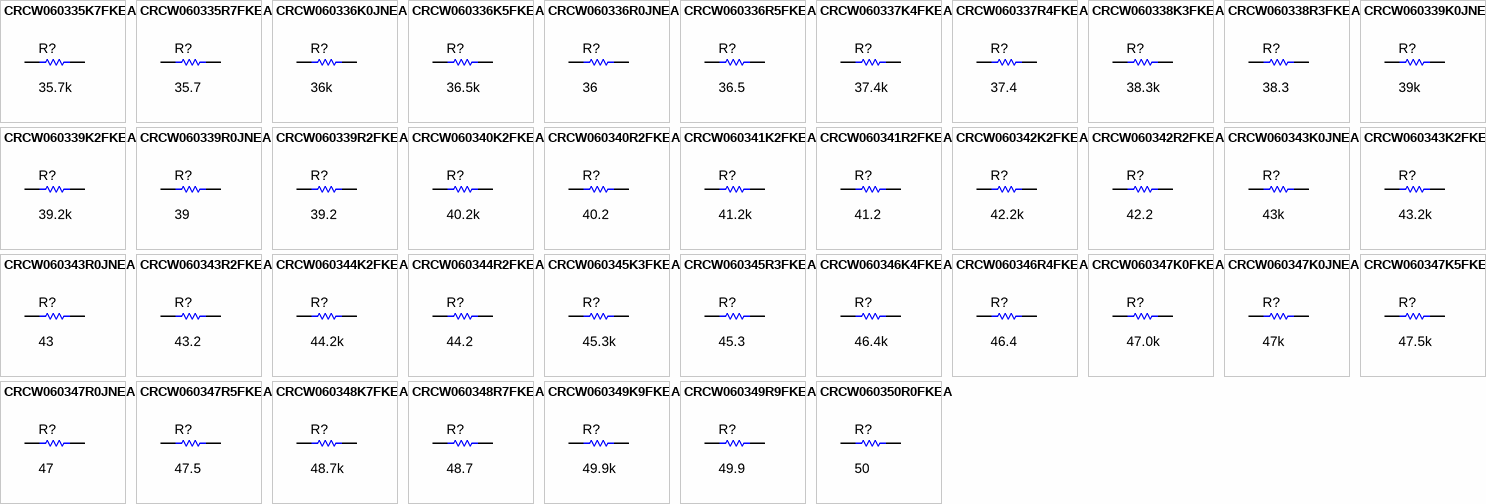
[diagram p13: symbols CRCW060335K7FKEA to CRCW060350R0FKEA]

## CRCW060335K7FKEA
designator R?  ValueDisplayed: 35.7k  (hidden comment: CRCW060335K7FKEA)
RES, 35.7 k, 1%, 0.1 W, 0603; Manufacturer: Vishay-Dale; CompType: Resistor; Value: 35.7k; Res_ohm: 35700; Value_Code: 35k7; Tolerance_%: 1; Power_W: 0.1; Value2: 0.1W; VDC_V: 75; TempCo: 100 ppm/C; SizeArea_mm2: 1.28; SizeX_mm: 1.6; SizeY_mm: 0.8; EIA_Code: E96; U/M: EA; AEC Category: Q200; Green_Lifecycle: Active; Green_REACh: Passed
signal-integrity model Resistor
simulation model Resistor
footprint 0603
footprint 0603M
footprint 0603L
footprint 0603_HV
footprint 0603S
pins: 1, 2

## CRCW060335R7FKEA
designator R?  ValueDisplayed: 35.7  (hidden comment: CRCW060335R7FKEA)
RES, 35.7, 1%, 0.1 W, 0603; Manufacturer: Vishay-Dale; CompType: Resistor; Value: 35.7; Value_Code: 35R7; Tolerance_%: 1; Power_W: 0.1; Value2: 0.1W; VDC_V: 75; TempCo: 100 ppm/C; SizeArea_mm2: 1.28; SizeX_mm: 1.6; SizeY_mm: 0.8; EIA_Code: E96; U/M: EA; AEC Category: Q200
signal-integrity model Resistor
simulation model Resistor
footprint 0603
footprint 0603M
footprint 0603L
footprint 0603_HV
footprint 0603S
pins: 1, 2

## CRCW060336K0JNEA
designator R?  ValueDisplayed: 36k  (hidden comment: CRCW060336K0JNEA)
RES, 36 k, 5%, 0.1 W, 0603; Manufacturer: Vishay-Dale; CompType: Resistor; Value: 36k; Res_ohm: 36000; Value_Code: 36k0; Tolerance_%: 5; Power_W: 0.1; Value2: 0.1W; VDC_V: 75; TempCo: 200 ppm/C; SizeArea_mm2: 1.28; SizeX_mm: 1.6; SizeY_mm: 0.8; SizeZ_mm: 1; EIA_Code: E24; U/M: EA; AEC Category: Q200
signal-integrity model Resistor
simulation model Resistor
footprint 0603
footprint 0603M
footprint 0603L
footprint 0603_HV
footprint 0603S
pins: 1, 2

## CRCW060336K5FKEA
designator R?  ValueDisplayed: 36.5k  (hidden comment: CRCW060336K5FKEA)
RES, 36.5 k, 1%, 0.1 W, 0603; Manufacturer: Vishay-Dale; CompType: Resistor; Value: 36.5k; Res_ohm: 36500; Value_Code: 36k5; Tolerance_%: 1; Power_W: 0.1; Value2: 0.1W; VDC_V: 75; TempCo: 100 ppm/C; SizeArea_mm2: 1.28; SizeX_mm: 1.6; SizeY_mm: 0.8; EIA_Code: E96; U/M: EA; AEC Category: Q200; Green_Lifecycle: Active; Green_REACh: Passed
signal-integrity model Resistor
simulation model Resistor
footprint 0603
footprint 0603M
footprint 0603L
footprint 0603_HV
footprint 0603S
pins: 1, 2

## CRCW060336R0JNEA
designator R?  ValueDisplayed: 36  (hidden comment: CRCW060336R0JNEA)
RES, 36, 5%, 0.1 W, 0603; Manufacturer: Vishay-Dale; CompType: Resistor; Value: 36; Value_Code: 36R0; Tolerance_%: 5; Power_W: 0.1; Value2: 0.1W; VDC_V: 75; TempCo: 200 ppm/C; SizeArea_mm2: 1.28; SizeX_mm: 1.6; SizeY_mm: 0.8; SizeZ_mm: 1; EIA_Code: E24; U/M: EA; AEC Category: Q200
signal-integrity model Resistor
simulation model Resistor
footprint 0603
footprint 0603M
footprint 0603L
footprint 0603_HV
footprint 0603S
pins: 1, 2

## CRCW060336R5FKEA
designator R?  ValueDisplayed: 36.5  (hidden comment: CRCW060336R5FKEA)
RES, 36.5, 1%, 0.1 W, 0603; Manufacturer: Vishay-Dale; CompType: Resistor; Value: 36.5; Value_Code: 36R5; Tolerance_%: 1; Power_W: 0.1; Value2: 0.1W; VDC_V: 75; TempCo: 100 ppm/C; SizeArea_mm2: 1.28; SizeX_mm: 1.6; SizeY_mm: 0.8; EIA_Code: E96; U/M: EA; AEC Category: Q200
signal-integrity model Resistor
simulation model Resistor
footprint 0603
footprint 0603M
footprint 0603L
footprint 0603_HV
footprint 0603S
pins: 1, 2

## CRCW060337K4FKEA
designator R?  ValueDisplayed: 37.4k  (hidden comment: CRCW060337K4FKEA)
RES, 37.4 k, 1%, 0.1 W, 0603; Manufacturer: Vishay-Dale; CompType: Resistor; Value: 37.4k; Res_ohm: 37400; Value_Code: 37k4; Tolerance_%: 1; Power_W: 0.1; Value2: 0.1W; VDC_V: 75; TempCo: 100 ppm/C; SizeArea_mm2: 1.28; SizeX_mm: 1.6; SizeY_mm: 0.8; EIA_Code: E96; U/M: EA; AEC Category: Q200; Green_Lifecycle: Active; Green_REACh: Passed
signal-integrity model Resistor
simulation model Resistor
footprint 0603
footprint 0603M
footprint 0603L
footprint 0603_HV
footprint 0603S
pins: 1, 2

## CRCW060337R4FKEA
designator R?  ValueDisplayed: 37.4  (hidden comment: CRCW060337R4FKEA)
RES, 37.4, 1%, 0.1 W, 0603; Manufacturer: Vishay-Dale; CompType: Resistor; Value: 37.4; Value_Code: 37R4; Tolerance_%: 1; Power_W: 0.1; Value2: 0.1W; VDC_V: 75; TempCo: 100 ppm/C; SizeArea_mm2: 1.28; SizeX_mm: 1.6; SizeY_mm: 0.8; EIA_Code: E96; U/M: EA; AEC Category: Q200
signal-integrity model Resistor
simulation model Resistor
footprint 0603
footprint 0603M
footprint 0603L
footprint 0603_HV
footprint 0603S
pins: 1, 2

## CRCW060338K3FKEA
designator R?  ValueDisplayed: 38.3k  (hidden comment: CRCW060338K3FKEA)
RES, 38.3 k, 1%, 0.1 W, 0603; Manufacturer: Vishay-Dale; CompType: Resistor; Value: 38.3k; Res_ohm: 38300; Value_Code: 38k3; Tolerance_%: 1; Power_W: 0.1; Value2: 0.1W; VDC_V: 75; TempCo: 100 ppm/C; SizeArea_mm2: 1.28; SizeX_mm: 1.6; SizeY_mm: 0.8; EIA_Code: E96; U/M: EA; AEC Category: Q200; Green_Lifecycle: Active; Green_REACh: Passed
signal-integrity model Resistor
simulation model Resistor
footprint 0603
footprint 0603M
footprint 0603L
footprint 0603_HV
footprint 0603S
pins: 1, 2

## CRCW060338R3FKEA
designator R?  ValueDisplayed: 38.3  (hidden comment: CRCW060338R3FKEA)
RES, 38.3, 1%, 0.1 W, 0603; Manufacturer: Vishay-Dale; CompType: Resistor; Value: 38.3; Value_Code: 38R3; Tolerance_%: 1; Power_W: 0.1; Value2: 0.1W; VDC_V: 75; TempCo: 100 ppm/C; SizeArea_mm2: 1.28; SizeX_mm: 1.6; SizeY_mm: 0.8; EIA_Code: E96; U/M: EA; AEC Category: Q200
signal-integrity model Resistor
simulation model Resistor
footprint 0603
footprint 0603M
footprint 0603L
footprint 0603_HV
footprint 0603S
pins: 1, 2

## CRCW060339K0JNEA
designator R?  ValueDisplayed: 39k  (hidden comment: CRCW060339K0JNEA)
RES, 39 k, 5%, 0.1 W, 0603; Manufacturer: Vishay-Dale; CompType: Resistor; Value: 39k; Res_ohm: 39000; Value_Code: 39k0; Tolerance_%: 5; Power_W: 0.1; Value2: 0.1W; VDC_V: 75; TempCo: 200 ppm/C; SizeArea_mm2: 1.28; SizeX_mm: 1.6; SizeY_mm: 0.8; SizeZ_mm: 1; EIA_Code: E24; U/M: EA; AEC Category: Q200; Green_Lifecycle: Active; Green_REACh: Passed
signal-integrity model Resistor
simulation model Resistor
footprint 0603
footprint 0603M
footprint 0603L
footprint 0603_HV
footprint 0603S
pins: 1, 2

## CRCW060339K2FKEA
designator R?  ValueDisplayed: 39.2k  (hidden comment: CRCW060339K2FKEA)
RES, 39.2 k, 1%, 0.1 W, 0603; Manufacturer: Vishay-Dale; CompType: Resistor; Value: 39.2k; Res_ohm: 39200; Value_Code: 39k2; Tolerance_%: 1; Power_W: 0.1; Value2: 0.1W; VDC_V: 75; TempCo: 100 ppm/C; SizeArea_mm2: 1.28; SizeX_mm: 1.6; SizeY_mm: 0.8; EIA_Code: E96; U/M: EA; AEC Category: Q200; Green_Lifecycle: Active; Green_REACh: Passed
signal-integrity model Resistor
simulation model Resistor
footprint 0603
footprint 0603M
footprint 0603L
footprint 0603_HV
footprint 0603S
pins: 1, 2

## CRCW060339R0JNEA
designator R?  ValueDisplayed: 39  (hidden comment: CRCW060339R0JNEA)
RES, 39, 5%, 0.1 W, 0603; Manufacturer: Vishay-Dale; CompType: Resistor; Value: 39; Value_Code: 39R0; Tolerance_%: 5; Power_W: 0.1; Value2: 0.1W; VDC_V: 75; TempCo: 200 ppm/C; SizeArea_mm2: 1.28; SizeX_mm: 1.6; SizeY_mm: 0.8; SizeZ_mm: 1; EIA_Code: E24; U/M: EA; AEC Category: Q200
signal-integrity model Resistor
simulation model Resistor
footprint 0603
footprint 0603M
footprint 0603L
footprint 0603_HV
footprint 0603S
pins: 1, 2

## CRCW060339R2FKEA
designator R?  ValueDisplayed: 39.2  (hidden comment: CRCW060339R2FKEA)
RES, 39.2, 1%, 0.1 W, 0603; Manufacturer: Vishay-Dale; CompType: Resistor; Value: 39.2; Value_Code: 39R2; Tolerance_%: 1; Power_W: 0.1; Value2: 0.1W; VDC_V: 75; TempCo: 100 ppm/C; SizeArea_mm2: 1.28; SizeX_mm: 1.6; SizeY_mm: 0.8; EIA_Code: E96; U/M: EA; AEC Category: Q200
signal-integrity model Resistor
simulation model Resistor
footprint 0603
footprint 0603M
footprint 0603L
footprint 0603_HV
footprint 0603S
pins: 1, 2

## CRCW060340K2FKEA
designator R?  ValueDisplayed: 40.2k  (hidden comment: CRCW060340K2FKEA)
RES, 40.2 k, 1%, 0.1 W, 0603; Manufacturer: Vishay-Dale; CompType: Resistor; Value: 40.2k; Res_ohm: 40200; Value_Code: 40k2; Tolerance_%: 1; Power_W: 0.1; Value2: 0.1W; VDC_V: 75; TempCo: 100 ppm/C; SizeArea_mm2: 1.28; SizeX_mm: 1.6; SizeY_mm: 0.8; EIA_Code: E96; U/M: EA; AEC Category: Q200; Green_Lifecycle: Active; Green_REACh: Passed
signal-integrity model Resistor
simulation model Resistor
footprint 0603
footprint 0603M
footprint 0603L
footprint 0603_HV
footprint 0603S
pins: 1, 2

## CRCW060340R2FKEA
designator R?  ValueDisplayed: 40.2  (hidden comment: CRCW060340R2FKEA)
RES, 40.2, 1%, 0.1 W, 0603; Manufacturer: Vishay-Dale; CompType: Resistor; Value: 40.2; Value_Code: 40R2; Tolerance_%: 1; Power_W: 0.1; Value2: 0.1W; VDC_V: 75; TempCo: 100 ppm/C; SizeArea_mm2: 1.28; SizeX_mm: 1.6; SizeY_mm: 0.8; EIA_Code: E96; U/M: EA; AEC Category: Q200; Green_Lifecycle: Active; Green_REACh: Passed
signal-integrity model Resistor
simulation model Resistor
footprint 0603
footprint 0603M
footprint 0603L
footprint 0603_HV
footprint 0603S
pins: 1, 2

## CRCW060341K2FKEA
designator R?  ValueDisplayed: 41.2k  (hidden comment: CRCW060341K2FKEA)
RES, 41.2 k, 1%, 0.1 W, 0603; Manufacturer: Vishay-Dale; CompType: Resistor; Value: 41.2k; Res_ohm: 41200; Value_Code: 41k2; Tolerance_%: 1; Power_W: 0.1; Value2: 0.1W; VDC_V: 75; TempCo: 100 ppm/C; SizeArea_mm2: 1.28; SizeX_mm: 1.6; SizeY_mm: 0.8; EIA_Code: E96; U/M: EA; AEC Category: Q200
signal-integrity model Resistor
simulation model Resistor
footprint 0603
footprint 0603M
footprint 0603L
footprint 0603_HV
footprint 0603S
pins: 1, 2

## CRCW060341R2FKEA
designator R?  ValueDisplayed: 41.2  (hidden comment: CRCW060341R2FKEA)
RES, 41.2, 1%, 0.1 W, 0603; Manufacturer: Vishay-Dale; CompType: Resistor; Value: 41.2; Value_Code: 41R2; Tolerance_%: 1; Power_W: 0.1; Value2: 0.1W; VDC_V: 75; TempCo: 100 ppm/C; SizeArea_mm2: 1.28; SizeX_mm: 1.6; SizeY_mm: 0.8; EIA_Code: E96; U/M: EA; AEC Category: Q200
signal-integrity model Resistor
simulation model Resistor
footprint 0603
footprint 0603M
footprint 0603L
footprint 0603_HV
footprint 0603S
pins: 1, 2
